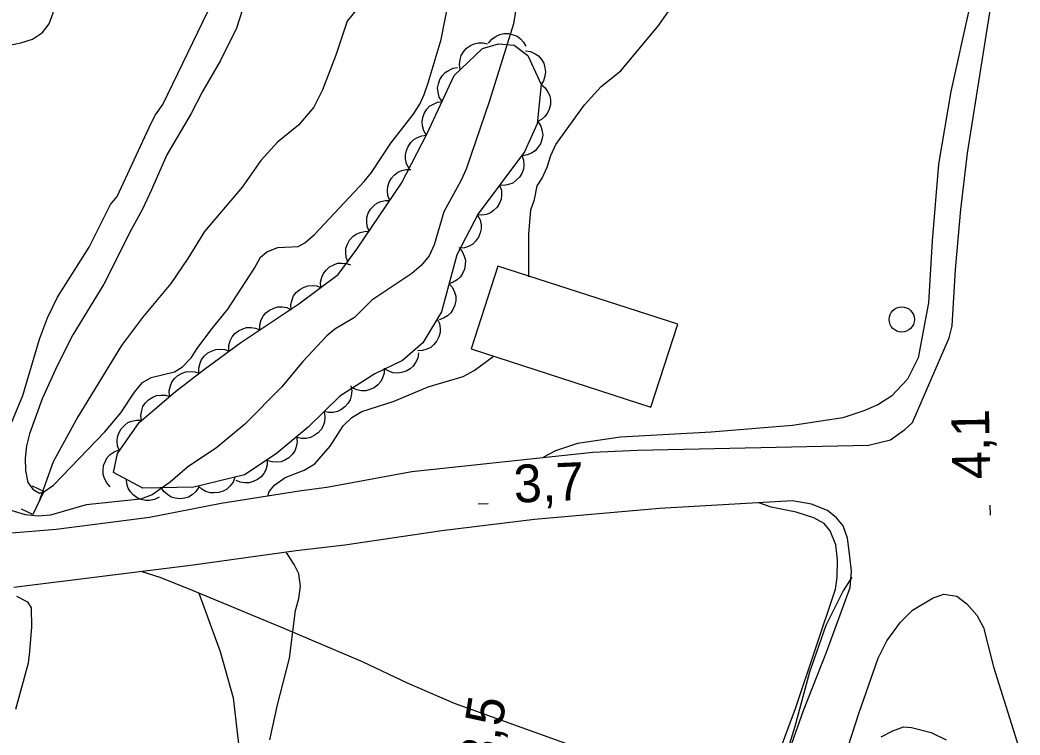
# Model space of a CAD drawing. Extents: x 282461 to 284471, y 5554090 to 5557646.
# Drawn here: x 283275.7 to 283355, y 5554882.8 to 5554939.5 of the extents above; entities that cross this region are included whole.
import ezdxf

# ---------------------------------------------------------------- set-up
doc = ezdxf.new("R2010")
doc.units = 0
for name, color, linetype in [('Niveau 2', 7, 'Continuous'), ('Niveau 21', 7, 'Continuous'), ('Niveau 22', 7, 'Continuous'), ('Niveau 26', 7, 'Continuous'), ('Niveau 3', 7, 'Continuous'), ('Niveau 31', 7, 'Continuous'), ('Niveau 36', 7, 'Continuous'), ('Niveau 4', 7, 'Continuous'), ('Niveau 44', 7, 'Continuous'), ('Niveau 7', 7, 'Continuous')]:
    doc.layers.add(name, color=color, linetype=linetype)

msp = doc.modelspace()

# ---------------------------------------------------------------- linework, layer by layer
at = {"layer": 'Niveau 2'}
for points in [[(283274.81, 5554937.51), (283275.73, 5554937.69), (283276.66, 5554937.99), (283277.47, 5554938.52), (283277.98, 5554939.22), (283278.32, 5554940.09), (283278.48, 5554941.02), (283278.4, 5554942.93), (283278.16, 5554943.86), (283277.86, 5554944.79), (283276.85, 5554946.46), (283276.55, 5554947.39), (283276.54, 5554948.26), (283276.98, 5554950.12), (283276.85, 5554950.93), (283276.31, 5554952.78), (283275.59, 5554954.63)], [(283315.36, 5554942.69), (283314.82, 5554939.2), (283312.92, 5554933.09), (283311.07, 5554927.68), (283310.67, 5554926.8), (283309.3, 5554924.3), (283308.52, 5554921.68), (283308.13, 5554920.8), (283307.49, 5554920.04), (283306.75, 5554919.4), (283303.58, 5554917.28), (283302.2, 5554915.93), (283300.64, 5554914.99), (283300.01, 5554914.46), (283298.11, 5554912.42), (283296.45, 5554910.43), (283293.47, 5554907.44), (283291.28, 5554905.62), (283288.97, 5554904.04), (283287.59, 5554902.86), (283286.15, 5554901.86), (283285.23, 5554901.51), (283280.93, 5554901.06)], [(283274.43, 5554906.17), (283275.89, 5554909.72), (283277.23, 5554914.2), (283277.85, 5554915.89), (283278.65, 5554917.52), (283281.16, 5554921.49), (283282.86, 5554924.87), (283283.37, 5554925.51), (283286.09, 5554931.34), (283286.43, 5554931.98), (283287.01, 5554932.8), (283290.98, 5554941.02)], [(283316.03, 5554919.14), (283316.04, 5554922.54), (283316.19, 5554924.45), (283316.47, 5554925.27), (283316.69, 5554926.37), (283317.09, 5554926.96), (283317.49, 5554927.83), (283317.77, 5554928.76), (283318.16, 5554929.63), (283320.45, 5554932.79), (283321.77, 5554934.25), (283323.32, 5554935.48), (283326.35, 5554939.1), (283327.32, 5554940.5)], [(283295.33, 5554901.75), (283295.44, 5554902.12), (283295.89, 5554902.64), (283296.7, 5554903.23), (283298.2, 5554903.82), (283299.07, 5554904.3), (283300.27, 5554905.7), (283301.3, 5554907.33), (283301.99, 5554907.98), (283302.79, 5554908.45), (283305.34, 5554909.28), (283308.05, 5554910.41), (283310.83, 5554911.24), (283311.7, 5554911.72), (283313.21, 5554912.82)], [(283280.93, 5554901.06), (283278.1, 5554900.23), (283277.11, 5554900.16), (283276.12, 5554900.27), (283274.26, 5554900.83)], [(283295.5, 5554882.41), (283296.1, 5554885.19), (283297.05, 5554888.91), (283297.52, 5554892.69), (283297.8, 5554893.62), (283297.91, 5554894.6), (283297.78, 5554895.59), (283297.42, 5554896.34), (283296.89, 5554897.14), (283296.79, 5554897.23)], [(283341.64, 5554895.32), (283340.95, 5554894.24), (283339.59, 5554891.5), (283338.3, 5554887.78), (283337.13, 5554883.48), (283335.51, 5554878.25)], [(283275.39, 5554893.82), (283276.26, 5554893.36), (283276.56, 5554892.9), (283276.58, 5554891.39), (283276.43, 5554889.42), (283276.32, 5554888.49), (283275.32, 5554884.83)]]:
    msp.add_lwpolyline(points, dxfattribs=at)
at = {"layer": 'Niveau 21'}
for points in [[(283362.78, 5555001.04), (283359.57, 5554986.05), (283358.55, 5554978.97), (283357.46, 5554972.93), (283356.14, 5554966.48), (283354.87, 5554961.19), (283350.94, 5554940.4), (283349.51, 5554933.84), (283348.53, 5554928.09), (283348.01, 5554922.01), (283347.72, 5554917.08), (283346.91, 5554912.72), (283346.06, 5554911.03), (283344.8, 5554909.69), (283343.7, 5554908.98), (283342.61, 5554908.51), (283340.93, 5554907.97), (283336.93, 5554907.36), (283330.49, 5554906.83), (283323.3, 5554906.42), (283319.88, 5554905.93), (283318.15, 5554905.33), (283317.19, 5554904.83)], [(283270.49, 5554898.46), (283278.55, 5554899.13), (283285.96, 5554900.08), (283291.63, 5554901.19), (283297.82, 5554902.18), (283300, 5554902.46), (283306.76, 5554903.7), (283321.1, 5554905.25), (283324.64, 5554905.4), (283342.97, 5554905.79), (283344.71, 5554906.21), (283345.86, 5554907.03), (283346.45, 5554907.58), (283349.36, 5554914.31), (283349.61, 5554915.27), (283349.86, 5554919.73), (283350.3, 5554924.48), (283350.83, 5554928.95), (283353.23, 5554944.13), (283354.08, 5554948.48), (283354.68, 5554952.37), (283356.76, 5554962.77)], [(283334.26, 5554874.72), (283337.82, 5554884.75), (283339.63, 5554889.37), (283341.51, 5554894.51), (283341.63, 5554895.81), (283341.5, 5554896.96), (283341.31, 5554898.41), (283340.95, 5554899.39), (283340.42, 5554900.02), (283339.72, 5554900.6), (283338.45, 5554901.1), (283336.94, 5554901.37), (283326.38, 5554900.76), (283316.48, 5554899.91), (283309.14, 5554899.01), (283301.45, 5554897.87), (283297.58, 5554897.42), (283289.42, 5554896.28), (283275.18, 5554894.5)], [(283324.93, 5554850.07), (283324.87, 5554851.06), (283325.54, 5554853.33), (283326.5, 5554856.18), (283330.6, 5554867.05), (283332.46, 5554872.4), (283334.31, 5554877.16), (283337.17, 5554884.91), (283340.36, 5554894.38), (283340.48, 5554895.3), (283340.52, 5554896.69), (283340.39, 5554897.9), (283339.92, 5554899), (283339.45, 5554899.58), (283338.63, 5554900.03), (283337.23, 5554900.48), (283335.25, 5554900.87), (283334.26, 5554901.21)], [(283340.83, 5554880.26), (283342.2, 5554884.51), (283343.74, 5554888.9), (283344.42, 5554890.27), (283345.5, 5554891.76), (283346.46, 5554892.7), (283348.1, 5554893.68), (283348.94, 5554893.98), (283349.98, 5554893.82), (283350.77, 5554893.22), (283351.56, 5554892.3), (283352.09, 5554891.34), (283352.88, 5554888.22), (283354.87, 5554881.9)], [(283343.96, 5554882.67), (283344.91, 5554883.14), (283345.75, 5554883.44), (283346.39, 5554883.39), (283347.95, 5554883), (283349.12, 5554882.43)]]:
    msp.add_lwpolyline(points, dxfattribs=at)
at = {"layer": 'Niveau 22'}
for points in [[(283285.33, 5554895.77), (283286.77, 5554895.31), (283289.34, 5554894.29), (283296.66, 5554891.26), (283302.82, 5554888.63), (283306.37, 5554886.93), (283310.1, 5554885.34), (283320.85, 5554881.47), (283325.83, 5554879.3), (283330.41, 5554876.77), (283333.41, 5554874.85)], [(283289.87, 5554894.06), (283291.55, 5554889.44), (283292.57, 5554885.75), (283293.07, 5554881.65), (283293.57, 5554879.1), (283293.72, 5554875.52), (283293.69, 5554873.26), (283293.24, 5554871.46), (283292.51, 5554869.6), (283291.49, 5554867.73), (283289.89, 5554865.4), (283288.7, 5554863.13), (283288.02, 5554861.27), (283287.59, 5554858.71), (283287.56, 5554856.51), (283288.04, 5554854.21), (283288.12, 5554852.13), (283287.17, 5554848.99), (283285.69, 5554846.09), (283284.96, 5554844.29), (283284.22, 5554842.1)]]:
    msp.add_lwpolyline(points, dxfattribs=at)
at = {"layer": 'Niveau 26'}
for p, q in [((283277.57, 5554902.11), (283276.67, 5554902.54)), ((283277.57, 5554902.11), (283276.7, 5554900.29)), ((283276.7, 5554900.29), (283275.8, 5554900.72))]:
    msp.add_line(p, q, dxfattribs=at)
at = {"layer": 'Niveau 3'}
for p, q in [((283312.01, 5554901.13), (283312.81, 5554901.17)), ((283352.63, 5554900.23), (283352.61, 5554901.03))]:
    msp.add_line(p, q, dxfattribs=at)
at = {"layer": 'Niveau 31'}
msp.add_lwpolyline([(283327.84, 5554915.38), (283313.58, 5554920), (283311.45, 5554913.42), (283325.71, 5554908.8), (283327.84, 5554915.38)], dxfattribs=at)
at = {"layer": 'Niveau 36'}
msp.add_circle((283345.604, 5554915.764), 1, dxfattribs=at)
at = {"layer": 'Niveau 4'}
msp.add_lwpolyline([(283304.76, 5554943.23), (283304.66, 5554942.57), (283304.32, 5554941.64), (283302.53, 5554940.52), (283301.62, 5554939.41), (283300.72, 5554936.73), (283299.66, 5554933.98), (283298.97, 5554932.59), (283297.77, 5554931.18), (283296.1, 5554929.83), (283294.78, 5554928.37), (283293.29, 5554926.26), (283290.31, 5554922.75), (283289, 5554920.59), (283287.63, 5554918.61), (283285.39, 5554915.91), (283283.73, 5554913.69), (283280.26, 5554908.03), (283278.32, 5554904.47), (283277.14, 5554901.21)], dxfattribs=at)
at = {"layer": 'Niveau 44'}
for points in [[(283312.84, 5554937.67), (283313.1, 5554937.99), (283313.43, 5554938.22), (283313.72, 5554938.37), (283314.06, 5554938.43), (283314.43, 5554938.43), (283314.79, 5554938.34), (283315.1, 5554938.23), (283315.37, 5554938.02), (283315.62, 5554937.75), (283315.79, 5554937.44)], [(283317.01, 5554934.4), (283316.7, 5554931.27), (283315.68, 5554929.05), (283312.02, 5554924.15), (283310.32, 5554920.89), (283309.1, 5554916.36), (283307.62, 5554913.91), (283306.01, 5554912.5), (283303.82, 5554911.44), (283301.05, 5554909.67), (283298.52, 5554907.22), (283296, 5554905.11), (283293.48, 5554903.44), (283289.46, 5554902.45), (283285.43, 5554902.37), (283283.09, 5554903.63), (283283.42, 5554905.14), (283285.13, 5554907.59), (283288.01, 5554910.06), (283290.31, 5554911.82), (283293.19, 5554913.93), (283297.8, 5554916.99), (283300.91, 5554919.34), (283302.4, 5554921.33), (283305.94, 5554926.58), (283307.95, 5554930.46), (283310.1, 5554935.12), (283312.35, 5554937.25), (283313.63, 5554937.61), (283314.88, 5554937.51), (283315.94, 5554936.71), (283317.01, 5554934.4)], [(283310.59, 5554935.59), (283310.53, 5554935.99), (283310.58, 5554936.39), (283310.66, 5554936.71), (283310.85, 5554937), (283311.09, 5554937.27), (283311.4, 5554937.48), (283311.69, 5554937.63), (283312.03, 5554937.69), (283312.4, 5554937.7), (283312.74, 5554937.62)], [(283315.77, 5554937.08), (283316.17, 5554937.02), (283316.53, 5554936.84), (283316.8, 5554936.66), (283317.03, 5554936.39), (283317.21, 5554936.08), (283317.31, 5554935.71), (283317.36, 5554935.4), (283317.31, 5554935.05), (283317.19, 5554934.7), (283317.01, 5554934.4)], [(283309.15, 5554933.05), (283308.93, 5554933.4), (283308.83, 5554933.79), (283308.8, 5554934.12), (283308.86, 5554934.46), (283308.98, 5554934.8), (283309.19, 5554935.11), (283309.4, 5554935.36), (283309.7, 5554935.54), (283310.03, 5554935.68), (283310.38, 5554935.74)], [(283317.01, 5554934.4), (283317.33, 5554934.14), (283317.55, 5554933.8), (283317.69, 5554933.51), (283317.74, 5554933.17), (283317.74, 5554932.8), (283317.64, 5554932.44), (283317.52, 5554932.14), (283317.3, 5554931.87), (283317.03, 5554931.62), (283316.72, 5554931.46)], [(283307.91, 5554930.36), (283307.69, 5554930.72), (283307.59, 5554931.11), (283307.56, 5554931.43), (283307.62, 5554931.77), (283307.74, 5554932.11), (283307.95, 5554932.43), (283308.16, 5554932.67), (283308.46, 5554932.85), (283308.79, 5554932.99), (283309.15, 5554933.05)], [(283316.78, 5554931.44), (283316.99, 5554931.09), (283317.09, 5554930.7), (283317.13, 5554930.38), (283317.07, 5554930.03), (283316.95, 5554929.69), (283316.73, 5554929.38), (283316.53, 5554929.13), (283316.23, 5554928.95), (283315.89, 5554928.81), (283315.54, 5554928.75)], [(283306.54, 5554927.74), (283306.34, 5554928.1), (283306.26, 5554928.49), (283306.24, 5554928.82), (283306.32, 5554929.16), (283306.45, 5554929.49), (283306.68, 5554929.8), (283306.9, 5554930.03), (283307.2, 5554930.2), (283307.55, 5554930.32), (283307.9, 5554930.37)], [(283315.48, 5554928.79), (283315.62, 5554928.4), (283315.63, 5554928), (283315.6, 5554927.67), (283315.47, 5554927.35), (283315.28, 5554927.04), (283315.01, 5554926.78), (283314.75, 5554926.58), (283314.43, 5554926.47), (283314.07, 5554926.4), (283313.71, 5554926.42)], [(283305.02, 5554925.21), (283304.86, 5554925.59), (283304.83, 5554925.99), (283304.84, 5554926.32), (283304.96, 5554926.64), (283305.13, 5554926.96), (283305.39, 5554927.24), (283305.64, 5554927.44), (283305.96, 5554927.58), (283306.31, 5554927.66), (283306.67, 5554927.66)], [(283313.71, 5554926.42), (283313.85, 5554926.03), (283313.86, 5554925.63), (283313.83, 5554925.3), (283313.7, 5554924.98), (283313.51, 5554924.67), (283313.24, 5554924.41), (283312.98, 5554924.21), (283312.66, 5554924.1), (283312.3, 5554924.03), (283311.94, 5554924.05)], [(283303.36, 5554922.76), (283303.21, 5554923.14), (283303.17, 5554923.54), (283303.19, 5554923.86), (283303.3, 5554924.19), (283303.48, 5554924.51), (283303.74, 5554924.78), (283303.98, 5554924.99), (283304.3, 5554925.12), (283304.66, 5554925.21), (283305.02, 5554925.21)], [(283311.96, 5554924.03), (283312.16, 5554923.67), (283312.24, 5554923.28), (283312.26, 5554922.95), (283312.18, 5554922.62), (283312.04, 5554922.28), (283311.81, 5554921.98), (283311.59, 5554921.74), (283311.29, 5554921.57), (283310.94, 5554921.45), (283310.59, 5554921.41)], [(283301.71, 5554920.3), (283301.55, 5554920.68), (283301.52, 5554921.08), (283301.53, 5554921.41), (283301.65, 5554921.74), (283301.82, 5554922.06), (283302.08, 5554922.33), (283302.33, 5554922.54), (283302.65, 5554922.67), (283303.01, 5554922.75), (283303.36, 5554922.76)], [(283310.47, 5554921.46), (283310.74, 5554921.15), (283310.9, 5554920.78), (283311, 5554920.47), (283310.99, 5554920.12), (283310.93, 5554919.76), (283310.77, 5554919.42), (283310.61, 5554919.14), (283310.35, 5554918.91), (283310.04, 5554918.72), (283309.7, 5554918.6)], [(283299.54, 5554918.31), (283299.52, 5554918.72), (283299.62, 5554919.11), (283299.74, 5554919.41), (283299.95, 5554919.68), (283300.22, 5554919.93), (283300.56, 5554920.1), (283300.86, 5554920.22), (283301.2, 5554920.24), (283301.57, 5554920.21), (283301.9, 5554920.09)], [(283297.18, 5554916.52), (283297.16, 5554916.94), (283297.26, 5554917.32), (283297.38, 5554917.63), (283297.59, 5554917.9), (283297.86, 5554918.14), (283298.2, 5554918.32), (283298.5, 5554918.44), (283298.84, 5554918.46), (283299.21, 5554918.42), (283299.54, 5554918.31)], [(283309.7, 5554918.6), (283309.97, 5554918.29), (283310.14, 5554917.92), (283310.23, 5554917.61), (283310.23, 5554917.26), (283310.16, 5554916.9), (283310, 5554916.56), (283309.84, 5554916.28), (283309.58, 5554916.05), (283309.27, 5554915.86), (283308.93, 5554915.74)], [(283294.69, 5554914.93), (283294.69, 5554915.34), (283294.81, 5554915.72), (283294.95, 5554916.02), (283295.18, 5554916.28), (283295.47, 5554916.5), (283295.81, 5554916.66), (283296.12, 5554916.76), (283296.47, 5554916.76), (283296.83, 5554916.7), (283297.16, 5554916.56)], [(283308.77, 5554915.81), (283308.94, 5554915.44), (283309, 5554915.04), (283309, 5554914.72), (283308.9, 5554914.38), (283308.74, 5554914.06), (283308.49, 5554913.77), (283308.26, 5554913.55), (283307.95, 5554913.4), (283307.59, 5554913.3), (283307.24, 5554913.28)], [(283292.23, 5554913.29), (283292.23, 5554913.7), (283292.35, 5554914.08), (283292.49, 5554914.38), (283292.72, 5554914.64), (283293, 5554914.87), (283293.35, 5554915.02), (283293.65, 5554915.12), (283294, 5554915.12), (283294.36, 5554915.06), (283294.69, 5554914.93)], [(283289.87, 5554911.5), (283289.85, 5554911.91), (283289.96, 5554912.3), (283290.08, 5554912.6), (283290.3, 5554912.87), (283290.57, 5554913.11), (283290.91, 5554913.28), (283291.21, 5554913.39), (283291.56, 5554913.41), (283291.92, 5554913.37), (283292.26, 5554913.25)], [(283307.27, 5554913.11), (283307.22, 5554912.7), (283307.05, 5554912.34), (283306.87, 5554912.07), (283306.61, 5554911.84), (283306.29, 5554911.66), (283305.93, 5554911.55), (283305.61, 5554911.49), (283305.27, 5554911.54), (283304.92, 5554911.65), (283304.61, 5554911.82)], [(283287.53, 5554909.69), (283287.5, 5554910.1), (283287.6, 5554910.49), (283287.71, 5554910.8), (283287.93, 5554911.07), (283288.2, 5554911.32), (283288.53, 5554911.49), (283288.83, 5554911.61), (283289.18, 5554911.64), (283289.54, 5554911.6), (283289.88, 5554911.49)], [(283304.56, 5554911.91), (283304.55, 5554911.5), (283304.42, 5554911.12), (283304.28, 5554910.83), (283304.05, 5554910.57), (283303.76, 5554910.35), (283303.41, 5554910.2), (283303.1, 5554910.11), (283302.75, 5554910.11), (283302.39, 5554910.18), (283302.07, 5554910.32)], [(283301.92, 5554910.51), (283301.99, 5554910.1), (283301.94, 5554909.71), (283301.86, 5554909.39), (283301.68, 5554909.09), (283301.44, 5554908.82), (283301.13, 5554908.6), (283300.85, 5554908.45), (283300.51, 5554908.39), (283300.14, 5554908.38), (283299.79, 5554908.45)], [(283285.3, 5554907.74), (283285.26, 5554908.15), (283285.33, 5554908.54), (283285.43, 5554908.85), (283285.63, 5554909.14), (283285.88, 5554909.4), (283286.2, 5554909.59), (283286.5, 5554909.73), (283286.84, 5554909.77), (283287.21, 5554909.76), (283287.55, 5554909.66)], [(283299.79, 5554908.45), (283299.86, 5554908.05), (283299.82, 5554907.65), (283299.73, 5554907.33), (283299.55, 5554907.04), (283299.32, 5554906.76), (283299, 5554906.55), (283298.72, 5554906.39), (283298.38, 5554906.33), (283298.01, 5554906.32), (283297.67, 5554906.39)], [(283283.57, 5554905.35), (283283.42, 5554905.73), (283283.39, 5554906.13), (283283.41, 5554906.46), (283283.53, 5554906.79), (283283.71, 5554907.1), (283283.98, 5554907.37), (283284.22, 5554907.58), (283284.55, 5554907.7), (283284.91, 5554907.78), (283285.26, 5554907.78)], [(283297.61, 5554906.46), (283297.65, 5554906.05), (283297.57, 5554905.65), (283297.47, 5554905.35), (283297.27, 5554905.06), (283297.01, 5554904.8), (283296.69, 5554904.61), (283296.39, 5554904.48), (283296.05, 5554904.44), (283295.68, 5554904.46), (283295.34, 5554904.56)], [(283282.84, 5554902.5), (283282.56, 5554902.8), (283282.38, 5554903.16), (283282.27, 5554903.46), (283282.26, 5554903.81), (283282.3, 5554904.17), (283282.45, 5554904.52), (283282.6, 5554904.81), (283282.84, 5554905.05), (283283.15, 5554905.26), (283283.47, 5554905.39)], [(283295.28, 5554904.63), (283295.28, 5554904.22), (283295.16, 5554903.84), (283295.02, 5554903.55), (283294.79, 5554903.29), (283294.51, 5554903.06), (283294.16, 5554902.91), (283293.85, 5554902.81), (283293.51, 5554902.81), (283293.15, 5554902.87), (283292.82, 5554903)], [(283286.71, 5554901.68), (283286.35, 5554901.49), (283285.95, 5554901.41), (283285.63, 5554901.4), (283285.29, 5554901.48), (283284.96, 5554901.62), (283284.66, 5554901.85), (283284.43, 5554902.08), (283284.26, 5554902.38), (283284.14, 5554902.73), (283284.11, 5554903.08)], [(283292.71, 5554903.25), (283292.57, 5554902.86), (283292.32, 5554902.54), (283292.09, 5554902.31), (283291.79, 5554902.15), (283291.44, 5554902.03), (283291.07, 5554902), (283290.75, 5554902.01), (283290.42, 5554902.13), (283290.1, 5554902.3), (283289.83, 5554902.54)], [(283289.85, 5554902.46), (283289.62, 5554902.11), (283289.32, 5554901.85), (283289.04, 5554901.68), (283288.71, 5554901.58), (283288.34, 5554901.54), (283287.97, 5554901.6), (283287.66, 5554901.68), (283287.37, 5554901.87), (283287.09, 5554902.11), (283286.89, 5554902.4)]]:
    msp.add_lwpolyline(points, dxfattribs=at)
at = {"layer": 'Niveau 7'}
for points in [[(283294.85, 5554945.16), (283292.84, 5554938.87), (283291.59, 5554936.3), (283290.16, 5554933.85), (283289.26, 5554932.1), (283287.32, 5554928.83), (283286.07, 5554925.98)], [(283286.07, 5554925.98), (283285.39, 5554924.52), (283284.48, 5554922.88), (283282.32, 5554918.57), (283279.87, 5554914.54), (283278.62, 5554912.09), (283277.44, 5554909.47), (283276.42, 5554906.68), (283276.2, 5554905.74), (283276.1, 5554904.76), (283276.11, 5554903.77), (283276.29, 5554902.84), (283276.71, 5554902.27), (283277.23, 5554901.98), (283277.58, 5554902.1), (283278.33, 5554902.63), (283282.41, 5554906.84), (283283.67, 5554908.37), (283284.75, 5554910), (283285.38, 5554910.76), (283286.07, 5554911.17), (283287.93, 5554911.6), (283288.56, 5554912.01), (283289.25, 5554912.71), (283289.77, 5554913.53), (283290.91, 5554915.05), (283292.17, 5554916.57), (283294.28, 5554919.84), (283294.74, 5554920.71), (283295.26, 5554921.12), (283296.12, 5554921.48), (283297.75, 5554921.55), (283298.27, 5554921.85), (283299.02, 5554922.49), (283302.98, 5554926.71), (283303.55, 5554927.41), (283305.09, 5554929.75), (283306.87, 5554932.03), (283307.38, 5554932.85), (283307.72, 5554933.6), (283308.06, 5554934.53), (283309.07, 5554937.97), (283310.05, 5554942.97)]]:
    msp.add_lwpolyline(points, dxfattribs=at)

# ---------------------------------------------------------------- texts
at = {"layer": 'Niveau 3'}
for s, height, rotation, p in [('4,1  ', 3, 90.99176, (283352.62, 5554903.11)), ('3,7  ', 2.9999, 2.46978, (283314.89, 5554901.22)), ('3,5  ', 3, 81.09575, (283313.39, 5554880.1))]:
    msp.add_text(s, height=height, rotation=rotation, dxfattribs=at).set_placement(p)

doc.saveas('drawing.dxf')
